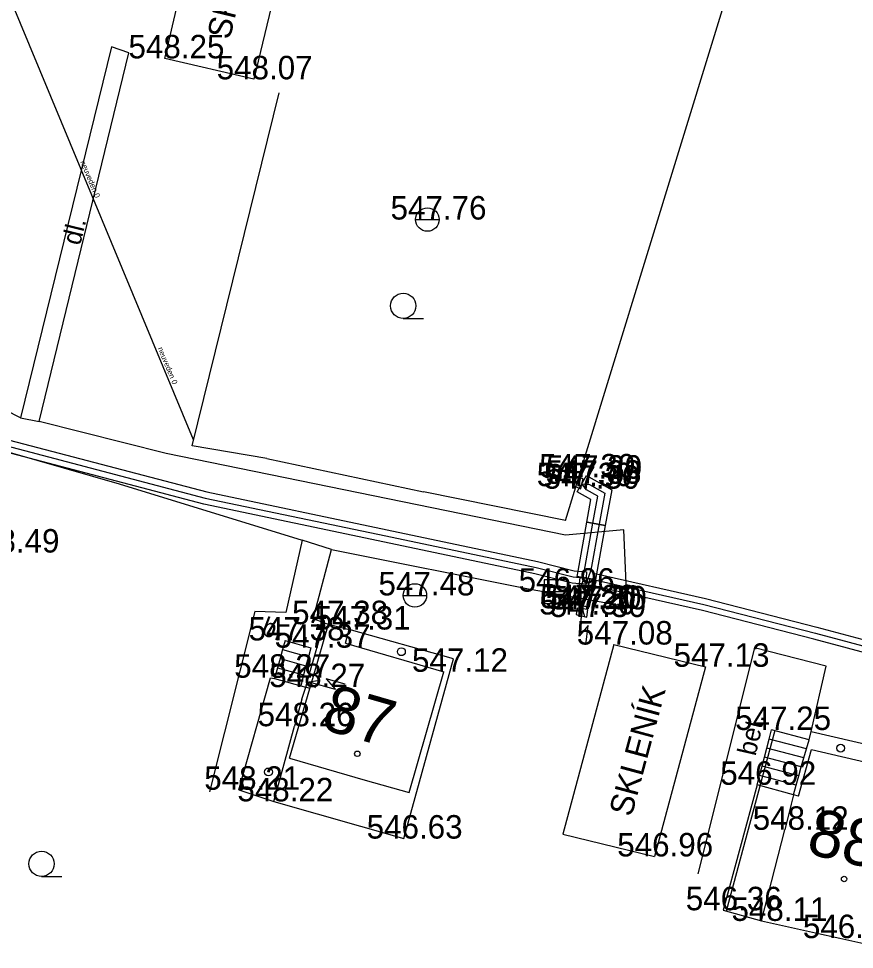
# Model space of a CAD drawing. Extents: x -669995 to -669686, y -1125551 to -1125263.
# Drawn here: x -669796.97 to -669770.25, y -1125355.41 to -1125325.67 of the extents above; entities that cross this region are included whole.
import ezdxf

# ---------------------------------------------------------------- set-up
doc = ezdxf.new("R2010")
doc.units = 0
for name, color, linetype in [('G_Bod_tecka', 7, 'Continuous'), ('G_Bod_vyska', 7, 'Continuous'), ('G_Budovy-znacky', 7, 'Continuous'), ('G_Budovy_Objekty', 7, 'Continuous'), ('G_Budovy_vstupy', 7, 'Continuous'), ('G_Cesty_Schody', 7, 'Continuous'), ('G_Cisla_popisna', 7, 'Continuous'), ('G_Objekty-Studny', 7, 'Continuous'), ('G_Plochy_zpevnene', 7, 'Continuous'), ('G_Ploty', 7, 'Continuous'), ('G_Ploty_vstupy', 7, 'Continuous'), ('G_Popisy_povrchu', 7, 'Continuous'), ('G_Poznamky_odkaz', 7, 'Continuous'), ('G_Site-kanalizace', 7, 'Continuous'), ('G_Site-Rozvadece', 7, 'Continuous'), ('G_Z_CHRANICKA-TEPLOVOD_kotovane', 7, 'Continuous'), ('G_Z_ELsilove_podz_kotovane', 7, 'Continuous'), ('G_Z_KANAL_podz_priblizne', 7, 'Continuous'), ('G_Zabradli_Svodidla', 7, 'Continuous'), ('G_Zelen-Znacky', 7, 'Continuous'), ('Vrstva 17', 7, 'Continuous'), ('Vrstva 3', 7, 'Continuous')]:
    doc.layers.add(name, color=color, linetype=linetype)

msp = doc.modelspace()

# ---------------------------------------------------------------- linework, layer by layer
at = {"layer": 'G_Bod_tecka'}
for p, q in [((-669792.29, -1125326.94), (-669792.29, -1125326.94)), ((-669789.45, -1125327.61), (-669789.45, -1125327.61)), ((-669783.9, -1125332.09), (-669783.9, -1125332.09)), ((-669779.14, -1125340.33), (-669779.14, -1125340.33)), ((-669778.92, -1125340.37), (-669778.92, -1125340.37)), ((-669779.22, -1125340.61), (-669779.22, -1125340.61)), ((-669779, -1125340.69), (-669779, -1125340.69)), ((-669778.96, -1125340.53), (-669778.96, -1125340.53)), ((-669779.79, -1125343.98), (-669779.79, -1125343.98)), ((-669784.3, -1125344.1), (-669784.3, -1125344.1)), ((-669779.11, -1125344.51), (-669779.11, -1125344.51)), ((-669778.94, -1125344.53), (-669778.94, -1125344.53)), ((-669778.77, -1125344.55), (-669778.77, -1125344.55)), ((-669779.14, -1125344.71), (-669779.14, -1125344.71)), ((-669778.8, -1125344.79), (-669778.8, -1125344.79)), ((-669787.06, -1125345.02), (-669787.06, -1125345.02)), ((-669786.4, -1125345.19), (-669786.4, -1125345.19)), ((-669788.45, -1125345.54), (-669788.45, -1125345.54)), ((-669787.62, -1125345.77), (-669787.62, -1125345.77)), ((-669777.94, -1125345.67), (-669777.94, -1125345.67)), ((-669775.01, -1125346.38), (-669775.01, -1125346.38)), ((-669788.91, -1125346.73), (-669788.91, -1125346.73)), ((-669783.37, -1125346.54), (-669783.37, -1125346.54)), ((-669787.79, -1125347.03), (-669787.79, -1125347.03)), ((-669788.15, -1125348.28), (-669788.15, -1125348.28)), ((-669772.9, -1125348.4), (-669772.9, -1125348.4)), ((-669773.36, -1125350.15), (-669773.36, -1125350.15)), ((-669789.93, -1125350.31), (-669789.93, -1125350.31)), ((-669788.81, -1125350.68), (-669788.81, -1125350.68)), ((-669772.48, -1125351.59), (-669772.48, -1125351.59)), ((-669784.65, -1125351.87), (-669784.65, -1125351.87)), ((-669776.64, -1125352.44), (-669776.64, -1125352.44)), ((-669774.45, -1125354.16), (-669774.45, -1125354.16)), ((-669773.22, -1125354.5), (-669773.22, -1125354.5)), ((-669770.72, -1125355.05), (-669770.72, -1125355.05))]:
    msp.add_line(p, q, dxfattribs=at)
at = {"layer": 'G_Budovy-znacky'}
for centre, radius in [((-669784.73, -1125345.9), 0.125), ((-669786.14, -1125349.161), 0.0875), ((-669770.69, -1125348.98), 0.125), ((-669788.98, -1125349.74), 0.125), ((-669770.58, -1125353.161), 0.0875)]:
    msp.add_circle(centre, radius, dxfattribs=at)
at = {"layer": 'G_Budovy_Objekty'}
for p, q in [((-669787.68, -1125346.64), (-669787.2, -1125344.98)), ((-669787.54, -1125346.68), (-669787.06, -1125345.02)), ((-669787.2, -1125344.98), (-669787.06, -1125345.02)), ((-669787.06, -1125345.02), (-669786.4, -1125345.19)), ((-669786.52, -1125345.63), (-669786.4, -1125345.19)), ((-669783.07, -1125346.13), (-669786.4, -1125345.19)), ((-669786.52, -1125345.63), (-669783.37, -1125346.54)), ((-669784.65, -1125351.87), (-669783.07, -1125346.13)), ((-669789.93, -1125350.31), (-669788.91, -1125346.73)), ((-669788.91, -1125346.73), (-669788.79, -1125346.76)), ((-669787.79, -1125347.03), (-669787.68, -1125346.64)), ((-669787.66, -1125347.07), (-669787.54, -1125346.68)), ((-669784.48, -1125350.4), (-669783.37, -1125346.54)), ((-669788.79, -1125346.76), (-669787.95, -1125346.99)), ((-669787.95, -1125346.99), (-669787.79, -1125347.03)), ((-669787.91, -1125347.41), (-669787.79, -1125347.03)), ((-669788.31, -1125349.3), (-669787.66, -1125347.07)), ((-669788.81, -1125350.68), (-669788.15, -1125348.28)), ((-669771.7, -1125348.71), (-669771.63, -1125348.45)), ((-669771.63, -1125348.45), (-669769.1, -1125349.04)), ((-669771.78, -1125349), (-669771.7, -1125348.71)), ((-669772.04, -1125350.51), (-669771.62, -1125349.02)), ((-669771.87, -1125349.29), (-669771.78, -1125349)), ((-669771.62, -1125349.02), (-669769.22, -1125349.58)), ((-669788.31, -1125349.3), (-669786.81, -1125349.74)), ((-669771.95, -1125349.58), (-669771.87, -1125349.29)), ((-669772.03, -1125349.87), (-669771.95, -1125349.58)), ((-669785.89, -1125350), (-669784.48, -1125350.4)), ((-669772.11, -1125350.16), (-669772.03, -1125349.87)), ((-669773.36, -1125350.15), (-669774.45, -1125354.16)), ((-669772.2, -1125350.47), (-669773.36, -1125350.15)), ((-669772.2, -1125350.47), (-669772.11, -1125350.16)), ((-669789.93, -1125350.31), (-669788.81, -1125350.68)), ((-669772.2, -1125350.47), (-669772.27, -1125350.77)), ((-669772.04, -1125350.51), (-669772.2, -1125350.47)), ((-669788.81, -1125350.68), (-669784.65, -1125351.87)), ((-669773.22, -1125354.5), (-669772.48, -1125351.59)), ((-669774.45, -1125354.16), (-669773.22, -1125354.5)), ((-669773.22, -1125354.5), (-669771.5, -1125354.88)), ((-669770.72, -1125355.05), (-669769.08, -1125355.41))]:
    msp.add_line(p, q, dxfattribs=at)
at = {"layer": 'G_Budovy_vstupy'}
for p, q in [((-669787.91, -1125347.41), (-669788.15, -1125348.28)), ((-669786.81, -1125349.74), (-669785.89, -1125350)), ((-669772.27, -1125350.77), (-669772.48, -1125351.59))]:
    msp.add_line(p, q, dxfattribs=at)
msp.add_lwpolyline([(-669771.5, -1125354.88), (-669770.72, -1125355.05)], dxfattribs=at)
at = {"layer": 'G_Cesty_Schody'}
for p, q in [((-669792.29, -1125326.94), (-669790.91, -1125321.07)), ((-669788.06, -1125321.8), (-669789.45, -1125327.61)), ((-669789.45, -1125327.61), (-669792.29, -1125326.94)), ((-669788.45, -1125345.54), (-669788.53, -1125345.83)), ((-669788.45, -1125345.54), (-669787.62, -1125345.77)), ((-669788.53, -1125345.83), (-669788.61, -1125346.12)), ((-669788.53, -1125345.83), (-669787.7, -1125346.06)), ((-669787.62, -1125345.77), (-669787.7, -1125346.06)), ((-669777.94, -1125345.67), (-669779.57, -1125351.73)), ((-669777.94, -1125345.67), (-669775.01, -1125346.38)), ((-669788.61, -1125346.12), (-669788.69, -1125346.41)), ((-669788.61, -1125346.12), (-669787.78, -1125346.35)), ((-669787.7, -1125346.06), (-669787.78, -1125346.35)), ((-669788.69, -1125346.41), (-669788.79, -1125346.76)), ((-669788.69, -1125346.41), (-669787.86, -1125346.64)), ((-669787.78, -1125346.35), (-669787.86, -1125346.64)), ((-669775.01, -1125346.38), (-669776.64, -1125352.44)), ((-669787.86, -1125346.64), (-669787.95, -1125346.99)), ((-669772.98, -1125348.69), (-669772.9, -1125348.4)), ((-669771.7, -1125348.71), (-669772.9, -1125348.4)), ((-669773.05, -1125348.98), (-669772.98, -1125348.69)), ((-669771.78, -1125349), (-669772.98, -1125348.69)), ((-669773.13, -1125349.27), (-669773.05, -1125348.98)), ((-669771.87, -1125349.29), (-669773.05, -1125348.98)), ((-669773.2, -1125349.56), (-669773.13, -1125349.27)), ((-669771.95, -1125349.58), (-669773.13, -1125349.27)), ((-669773.28, -1125349.85), (-669773.2, -1125349.56)), ((-669772.03, -1125349.87), (-669773.2, -1125349.56)), ((-669773.36, -1125350.15), (-669773.28, -1125349.85)), ((-669772.11, -1125350.16), (-669773.28, -1125349.85)), ((-669779.57, -1125351.73), (-669776.64, -1125352.44))]:
    msp.add_line(p, q, dxfattribs=at)
for points in [[(-669796.9, -1125338.43), (-669799.27, -1125337.22), (-669803.77, -1125335.68), (-669813.94, -1125333.28), (-669817.15, -1125332.43), (-669818.19, -1125331.78)], [(-669818.64, -1125334.32), (-669817.84, -1125334.51), (-669812.78, -1125335.69), (-669801.7, -1125338.55), (-669798.17, -1125339.27), (-669793.75, -1125340.53), (-669787.9, -1125342.33)], [(-669786.96, -1125342.63), (-669780.67, -1125343.89), (-669777.51, -1125344.45), (-669777.62, -1125342), (-669779.49, -1125342.18), (-669792.25, -1125339.57), (-669796.31, -1125338.54)]]:
    msp.add_lwpolyline(points, dxfattribs=at)
at = {"layer": 'G_Objekty-Studny'}
for p, q in [((-669784.275, -1125332.09), (-669783.525, -1125332.09)), ((-669784.675, -1125344.1), (-669783.925, -1125344.1))]:
    msp.add_line(p, q, dxfattribs=at)
for centre in [(-669783.9, -1125332.09), (-669784.3, -1125344.1)]:
    msp.add_circle(centre, 0.375, dxfattribs=at)
at = {"layer": 'G_Plochy_zpevnene'}
for p, q in [((-669794, -1125326.57), (-669796.9, -1125338.43)), ((-669796.31, -1125338.54), (-669793.44, -1125326.76)), ((-669793.44, -1125326.76), (-669794, -1125326.57)), ((-669796.9, -1125338.43), (-669796.31, -1125338.54))]:
    msp.add_line(p, q, dxfattribs=at)
for points in [[(-669787.2, -1125344.98), (-669787.55, -1125344.85), (-669786.96, -1125342.63), (-669787.9, -1125342.33), (-669788.42, -1125344.65), (-669789.41, -1125344.61), (-669790.86, -1125350.38)], [(-669771.63, -1125348.45), (-669771.15, -1125346.36), (-669773.44, -1125345.78), (-669775.26, -1125353)]]:
    msp.add_lwpolyline(points, dxfattribs=at)
at = {"layer": 'G_Ploty'}
for p, q in [((-669791.42, -1125339.32), (-669788.64, -1125328.04)), ((-669789.03, -1125339.73), (-669791.42, -1125339.32)), ((-669779.49, -1125341.71), (-669784.02, -1125340.79))]:
    msp.add_line(p, q, dxfattribs=at)
msp.add_lwpolyline([(-669779.49, -1125341.71), (-669779.16, -1125340.63), (-669779.07, -1125340.34), (-669772.57, -1125319.2)], dxfattribs=at)
at = {"layer": 'G_Ploty_vstupy'}
msp.add_lwpolyline([(-669789.03, -1125339.73), (-669784.02, -1125340.79)], dxfattribs=at)
at = {"layer": 'G_Site-kanalizace'}
msp.add_line((-669780.165, -1125343.98), (-669779.415, -1125343.98), dxfattribs=at)
msp.add_lwpolyline([(-669780.165, -1125344.354), (-669779.415, -1125344.354), (-669779.415, -1125343.604), (-669780.165, -1125343.604)], close=True, dxfattribs=at)
at = {"layer": 'G_Site-Rozvadece'}
for p, q in [((-669778.94, -1125344.53), (-669779.081, -1125344.759)), ((-669779.053, -1125345.398), (-669778.94, -1125344.53)), ((-669778.863, -1125344.787), (-669778.94, -1125344.53)), ((-669778.757, -1125345.058), (-669779.053, -1125345.398)), ((-669778.838, -1125345.679), (-669778.757, -1125345.058)), ((-669787.68, -1125346.64), (-669787.54, -1125346.68)), ((-669787.66, -1125347.07), (-669787.79, -1125347.03)), ((-669787.415, -1125346.831), (-669787.68, -1125346.87)), ((-669786.839, -1125347.11), (-669787.68, -1125346.87)), ((-669787.68, -1125346.87), (-669787.475, -1125347.043)), ((-669786.529, -1125346.938), (-669787.131, -1125346.766)), ((-669787.131, -1125346.766), (-669786.839, -1125347.11))]:
    msp.add_line(p, q, dxfattribs=at)
msp.add_lwpolyline([(-669779, -1125340.69), (-669778.96, -1125340.53), (-669778.92, -1125340.37), (-669779.07, -1125340.34), (-669779.14, -1125340.33), (-669779.22, -1125340.61), (-669779.16, -1125340.63), (-669779, -1125340.69)], dxfattribs=at)
msp.add_lwpolyline([(-669778.8, -1125344.79), (-669778.77, -1125344.55), (-669778.94, -1125344.53), (-669779.11, -1125344.51), (-669779.14, -1125344.71)], close=True, dxfattribs=at)
at = {"layer": 'G_Z_CHRANICKA-TEPLOVOD_kotovane'}
msp.add_lwpolyline([(-669797.709, -1125339.017), (-669790.954, -1125340.795), (-669785.189, -1125342.004), (-669780.379, -1125343.014), (-669779.207, -1125343.312), (-669779.084, -1125343.322), (-669778.813, -1125343.344), (-669778.825, -1125343.537), (-669778.826, -1125343.549), (-669778.826, -1125343.549), (-669778.839, -1125343.745), (-669778.951, -1125343.735), (-669779.043, -1125343.727), (-669779.273, -1125343.708), (-669780.461, -1125343.406), (-669785.271, -1125342.396), (-669791.046, -1125341.185), (-669797.811, -1125339.403)], dxfattribs=at)
for points in [[(-669778.813, -1125340.269), (-669778.006, -1125340.724), (-669778.215, -1125341.863), (-669778.215, -1125341.864), (-669778.51, -1125341.81), (-669778.805, -1125341.756), (-669778.674, -1125341.036), (-669779.108, -1125340.791)], [(-669779.084, -1125343.322), (-669778.805, -1125341.757), (-669778.51, -1125341.81), (-669778.215, -1125341.863), (-669778.215, -1125341.864), (-669778.491, -1125343.412), (-669778.525, -1125343.603), (-669778.601, -1125343.589), (-669778.623, -1125343.585), (-669778.684, -1125343.574), (-669778.82, -1125343.55), (-669778.826, -1125343.549), (-669778.898, -1125343.536), (-669779.115, -1125343.497)], [(-669778.558, -1125343.397), (-669778.491, -1125343.412), (-669775.013, -1125344.196), (-669771.449, -1125345.117), (-669767.297, -1125346.217), (-669761.355, -1125347.898), (-669758.181, -1125348.819), (-669755.512, -1125349.708), (-669750.542, -1125351.059), (-669748.392, -1125351.786), (-669748.139, -1125352.039), (-669748.421, -1125352.321), (-669748.608, -1125352.134), (-669750.658, -1125351.441), (-669755.628, -1125350.091), (-669758.299, -1125349.201), (-669761.465, -1125348.282), (-669767.403, -1125346.603), (-669771.551, -1125345.503), (-669775.107, -1125344.584), (-669778.556, -1125343.807), (-669778.646, -1125343.787), (-669778.603, -1125343.596), (-669778.601, -1125343.589)], [(-669779.043, -1125343.727), (-669779.019, -1125343.526), (-669778.899, -1125343.54), (-669778.826, -1125343.549), (-669778.82, -1125343.55), (-669778.737, -1125343.56), (-669778.622, -1125343.574), (-669778.623, -1125343.585), (-669778.623, -1125343.59), (-669778.73, -1125344.464), (-669778.93, -1125344.44), (-669779.128, -1125344.416)], [(-669778.898, -1125343.536), (-669778.893, -1125343.519), (-669778.825, -1125343.537), (-669778.737, -1125343.56), (-669778.684, -1125343.574), (-669778.623, -1125343.59), (-669778.603, -1125343.596), (-669778.507, -1125343.621), (-669778.556, -1125343.807), (-669778.737, -1125344.491), (-669778.93, -1125344.44), (-669779.123, -1125344.389), (-669778.951, -1125343.735), (-669778.899, -1125343.54)]]:
    msp.add_lwpolyline(points, close=True, dxfattribs=at)
at = {"layer": 'G_Z_ELsilove_podz_kotovane'}
for points in [[(-669805.56, -1125338), (-669805.32, -1125337.74), (-669804.31, -1125337.62), (-669800.88, -1125338.38), (-669797.76, -1125339.21), (-669791, -1125340.99), (-669785.23, -1125342.2), (-669780.42, -1125343.21), (-669779.24, -1125343.51), (-669778.92, -1125343.54), (-669778.608, -1125341.792)], [(-669778.608, -1125341.792), (-669778.451, -1125340.932), (-669778.814, -1125340.727), (-669778.96, -1125340.53), (-669778.716, -1125340.553), (-669778.229, -1125340.828), (-669778.412, -1125341.828), (-669778.672, -1125343.292), (-669778.848, -1125343.782), (-669778.906, -1125344.254), (-669778.93, -1125344.44)], [(-669778.93, -1125344.44), (-669778.7, -1125343.57), (-669775.06, -1125344.39), (-669771.5, -1125345.31), (-669767.35, -1125346.41), (-669761.41, -1125348.09), (-669758.24, -1125349.01), (-669755.57, -1125349.9), (-669750.6, -1125351.25), (-669749.128, -1125351.748), (-669748.879, -1125351.832), (-669748.5, -1125351.96), (-669748.28, -1125352.18)]]:
    msp.add_lwpolyline(points, dxfattribs=at)
at = {"layer": 'G_Z_KANAL_podz_priblizne'}
msp.add_line((-669805.95, -1125304.06), (-669791.39, -1125339.12), dxfattribs=at)
at = {"layer": 'G_Zabradli_Svodidla'}
msp.add_line((-669772.8, -1125348.42), (-669774.35, -1125354.19), dxfattribs=at)
at = {"layer": 'G_Zelen-Znacky'}
for p, q in [((-669784.672, -1125335.25), (-669784.022, -1125335.247)), ((-669796.232, -1125353.08), (-669795.582, -1125353.077))]:
    msp.add_line(p, q, dxfattribs=at)
for centre in [(-669784.672, -1125334.847), (-669796.232, -1125352.677)]:
    msp.add_circle(centre, 0.403, dxfattribs=at)
at = {"layer": 'Vrstva 17'}
msp.add_line((-669805.95, -1125304.06), (-669791.39, -1125339.12), dxfattribs=at)

# ---------------------------------------------------------------- texts
at = {"layer": 'G_Bod_vyska'}
for s, p in [('548.25', (-669793.454, -1125326.94)), ('548.07', (-669790.636, -1125327.61)), ('547.76', (-669785.078, -1125332.09)), ('547.30', (-669780.326, -1125340.33)), ('547.30', (-669780.406, -1125340.61)), ('547.33', (-669780.124, -1125340.53)), ('547.30', (-669780.106, -1125340.37)), ('547.30', (-669780.186, -1125340.69)), ('548.49', (-669798.726, -1125342.73)), ('547.48', (-669785.464, -1125344.1)), ('546.96', (-669780.983, -1125343.98)), ('547.20', (-669780.296, -1125344.51)), ('547.30', (-669780.326, -1125344.71)), ('547.20', (-669780.126, -1125344.53)), ('547.30', (-669779.986, -1125344.79)), ('547.30', (-669779.956, -1125344.55)), ('547.38', (-669788.224, -1125345.02)), ('547.31', (-669787.502, -1125345.19)), ('547.38', (-669789.614, -1125345.54)), ('547.08', (-669779.126, -1125345.67)), ('547.37', (-669788.784, -1125345.77)), ('547.12', (-669784.392, -1125346.54)), ('547.13', (-669776.032, -1125346.38)), ('548.27', (-669790.074, -1125346.73)), ('548.27', (-669788.954, -1125347.03)), ('548.26', (-669789.328, -1125348.28)), ('547.25', (-669774.064, -1125348.4)), ('546.92', (-669774.54, -1125350.15)), ('548.21', (-669791.032, -1125350.31)), ('548.22', (-669789.974, -1125350.68)), ('548.12', (-669773.502, -1125351.59)), ('546.63', (-669785.842, -1125351.87)), ('546.96', (-669777.833, -1125352.44)), ('546.36', (-669775.642, -1125354.16)), ('548.11', (-669774.181, -1125354.5)), ('546.42', (-669771.898, -1125355.05))]:
    msp.add_text(s, height=0.75, dxfattribs=at).set_placement(p)
at = {"layer": 'G_Cisla_popisna'}
for s, rotation, p in [('87', 343.9611, (-669787.344, -1125348.348)), ('88', 346.8731, (-669771.831, -1125352.334))]:
    msp.add_text(s, height=1.5, rotation=rotation, dxfattribs=at).set_placement(p)
at = {"layer": 'G_Popisy_povrchu'}
for s, rotation, p in [('dl.', 76.3076, (-669795, -1125332.939)), ('b.', 339.6236, (-669789.254, -1125345.336)), ('bet.', 77.0655, (-669773.413, -1125349.253))]:
    msp.add_text(s, height=0.6, rotation=rotation, dxfattribs=at).set_placement(p)
at = {"layer": 'G_Poznamky_odkaz'}
for rotation, p in [(76.5453, (-669790.218, -1125326.365)), (74.9451, (-669777.378, -1125351.2))]:
    msp.add_text('SKLENÍK', height=0.75, rotation=rotation, dxfattribs=at).set_placement(p)
at = {"layer": 'Vrstva 3'}
for rotation, p in [(292.5541, (-669794.998, -1125330.248)), (292.5354, (-669792.523, -1125336.207))]:
    msp.add_text('neuveden 0', height=0.1755, rotation=rotation, dxfattribs=at).set_placement(p)

doc.saveas('drawing.dxf')
